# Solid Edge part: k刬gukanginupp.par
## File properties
Author: Türk
Template: Iso Part.par
Last saved by: Türk
Revision: 5
Application: Solid Edge
Accuracy: 0,990
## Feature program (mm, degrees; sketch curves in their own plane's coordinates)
sketch for "Hole_2" plane through (0, 0, 0) normal (0, -1, 0) x-axis (1, 0, 0)
  hole centre (0, 0) bore radius 4.594
hole "Hole_2" nominal diameter 10 finite
pattern "unnamed Pattern 1" of "Hole_2"
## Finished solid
Body 1: solid body, 3 faces, 2 edges, 0 vertices.
  Faces by surface: cylinder 1, plane 1, sphere 1
  Edges by curve: circle 2
Body 2: sheet body, 1 face, 1 edge, 0 vertices.
  Faces by surface: plane 1
  Edges by curve: circle 1
Bounding box of the edges (mm; curved faces can reach further): 50.000 x 24.574 x 50.000, from (-25, 0, -25) to (25, 24.5743, 25).
Cylindrical faces by radius (mm): R4.594 x1
Spherical faces by radius (mm): R25 x1
Planar faces by outward normal: +y 1
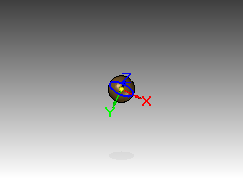
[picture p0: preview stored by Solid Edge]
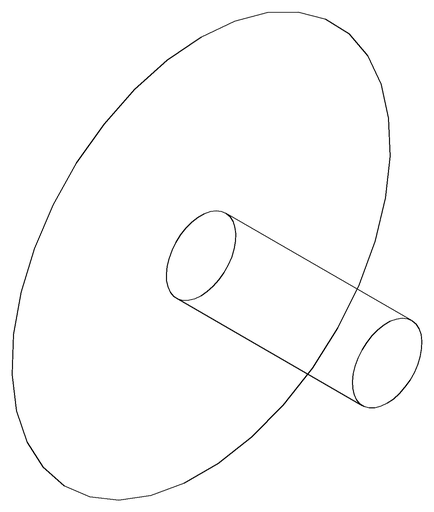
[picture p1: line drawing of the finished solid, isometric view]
